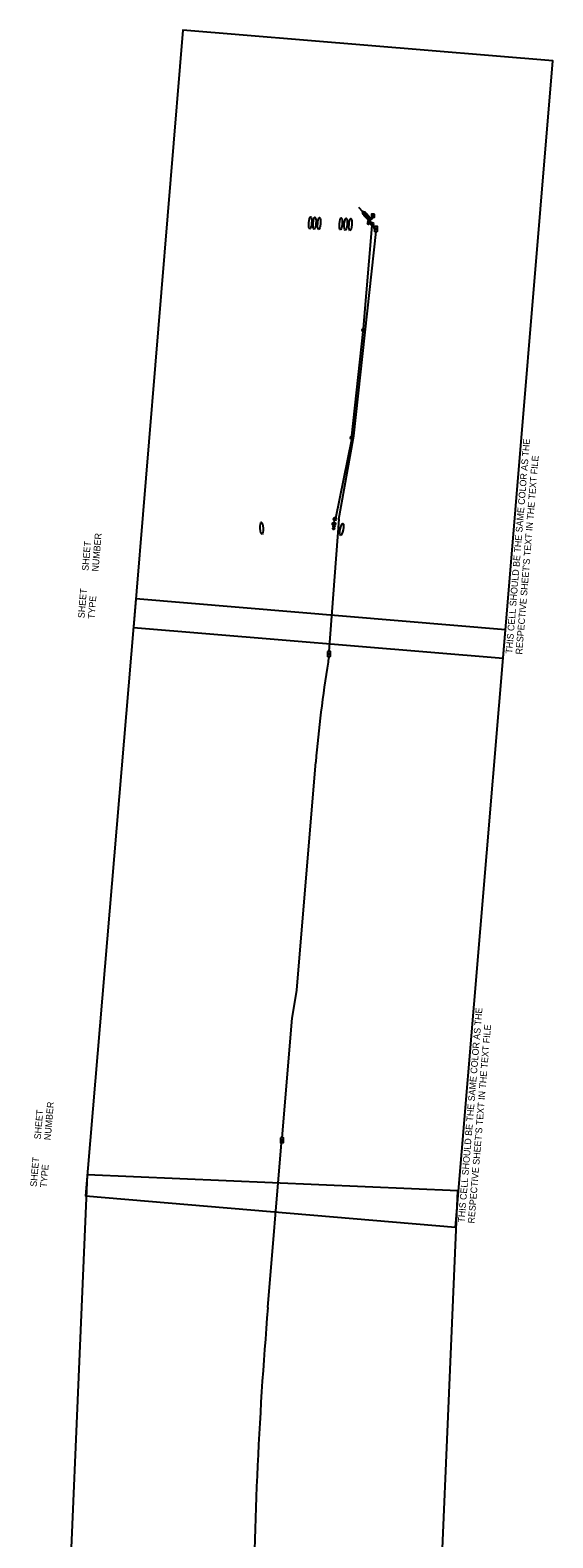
# Model space of a CAD drawing. Extents: x 601462 to 605493, y 331960 to 402715.
# Drawn here: x 602529 to 603902, y 398753 to 402715 of the extents above; entities that cross this region are included whole.
import ezdxf

# ---------------------------------------------------------------- set-up
doc = ezdxf.new("R2010")
doc.units = 0
for name, color, linetype in [('Default', 7, 'Continuous'), ('E_FTMS', 7, 'Continuous'), ('P_FTMS', 7, 'Continuous'), ('P_FTMSConduit', 7, 'Continuous'), ('P_MISC_TXT_1A (Construction)', 7, 'Continuous'), ('P_MISC_TXT_1B (Construction)', 7, 'Continuous')]:
    doc.layers.add(name, color=color, linetype=linetype)

# ---------------------------------------------------------------- blocks, each defined once
blk = doc.blocks.new('POINT_DISPLAY')
at = {"layer": 'Default'}
blk.add_line((0, 0), (0, 0), dxfattribs=at)
blk = doc.blocks.new('_U229')
at = {"layer": 'P_FTMS'}
for p, q in [((-5, 3), (2, 0)), ((-2, 3), (-4, 0)), ((-2, 3), (-4, 0)), ((-2, 3), (-4, 1)), ((-3, 3), (-4, 1)), ((-3, 3), (-4, 1)), ((-3, 3), (-4, 2)), ((-4, 3), (-4, 2)), ((-4, 3), (-4, 3)), ((-4, 3), (2, 0)), ((-4, 3), (2, 0)), ((-4, 3), (1, 0)), ((-4, 2), (1, -1)), ((-4, 2), (1, -1)), ((-4, 2), (0, -1)), ((-4, 1), (0, -1)), ((-4, 1), (0, -1)), ((-4, 0), (0, -2)), ((1, 3), (-3, -3)), ((0, 3), (-3, -3)), ((0, 3), (-3, -2)), ((0, 3), (-3, -2)), ((-1, 3), (-3, -2)), ((-1, 3), (-3, -1)), ((-1, 3), (-3, -1)), ((-3, 3), (2, 0)), ((1, 3), (-2, -3)), ((1, 3), (-2, -3)), ((-2, 3), (3, 1)), ((2, 3), (-1, -2)), ((2, 3), (-1, -2)), ((-1, 3), (3, 1)), ((2, 3), (0, -1)), ((0, 3), (3, 1)), ((3, 3), (1, -1)), ((1, 3), (4, 1)), ((1, 3), (3, 1)), ((3, 2), (1, 0)), ((2, 3), (4, 2)), ((3, 2), (2, 0)), ((4, 2), (3, 1)), ((4, 2), (3, 1)), ((3, 2), (4, 2)), ((4, 2), (4, 2)), ((4, 2), (4, 2)), ((-4, 0), (-1, -2)), ((-3, 0), (-1, -2)), ((-3, -1), (-1, -2)), ((-3, -1), (-1, -2)), ((-3, -2), (-2, -3)), ((-3, -2), (-2, -3)), ((-3, -3), (-2, -3)), ((-3, -3), (-2, -3)), ((-3, -3), (-3, -3))]:
    blk.add_line(p, q, dxfattribs=at)
blk.add_lwpolyline([(-5, 4), (5, 2), (-3, -4)], close=True, dxfattribs=at)
blk.add_blockref('POINT_DISPLAY', (5, 2), dxfattribs=at)
blk = doc.blocks.new('FMD')
at = {"layer": 'P_FTMS'}
for p, q in [((17, 18), (-17, 18)), ((-16, 16), (-16, 18)), ((16, 16), (-16, 16)), ((-15, 15), (-15, 20)), ((15, 19), (-15, 19)), ((15, 15), (-15, 15)), ((14, 20), (-14, 20)), ((13, 22), (-13, 22)), ((-13, 13), (-13, 21)), ((13, 13), (-13, 13)), ((-12, 12), (-12, 23)), ((12, 12), (-12, 12)), ((11, 23), (-11, 23)), ((10, 25), (-10, 25)), ((-10, 10), (-10, 24)), ((10, 10), (-10, 10)), ((-9, 9), (-9, 26)), ((9, 9), (-9, 9)), ((8, 26), (-8, 26)), ((7, 28), (-7, 28)), ((-7, 7), (-7, 27)), ((7, 7), (-7, 7)), ((-6, 6), (-6, 29)), ((6, 6), (-6, 6)), ((5, 29), (-5, 29)), ((4, 31), (-4, 31)), ((-4, 4), (-4, 30)), ((4, 4), (-4, 4)), ((-3, 3), (-3, 32)), ((3, 3), (-3, 3)), ((2, 32), (-2, 32)), ((1, 34), (-1, 34)), ((-1, 1), (-1, 33)), ((1, 1), (-1, 1)), ((0, 0), (0, 34)), ((1, 1), (1, 33)), ((3, 3), (3, 32)), ((4, 4), (4, 30)), ((6, 6), (6, 29)), ((7, 7), (7, 27)), ((9, 9), (9, 26)), ((10, 10), (10, 24)), ((12, 12), (12, 23)), ((13, 13), (13, 21)), ((15, 15), (15, 20)), ((16, 16), (16, 18))]:
    blk.add_line(p, q, dxfattribs=at)
blk.add_lwpolyline([(-17, 17), (0, 34), (17, 17), (0, 0)], close=True, dxfattribs=at)
blk = doc.blocks.new('FMB_2')
at = {"layer": 'P_FTMS'}
for p, q in [((24, -24), (-24, 24)), ((-24, -24), (24, 24))]:
    blk.add_line(p, q, dxfattribs=at)
blk.add_lwpolyline([(24, -24), (24, 24), (-24, 24), (-24, -24)], close=True, dxfattribs=at)
blk = doc.blocks.new('FTMS_FCV')
at = {"layer": 'P_FTMS'}
blk.add_line((13, 16), (1, -22), dxfattribs=at)
blk.add_lwpolyline([(39, 24), (-39, 24), (-39, -24), (39, -24)], close=True, dxfattribs=at)
blk.add_lwpolyline([(-12, 16), (1, -22)], dxfattribs=at)
blk = doc.blocks.new('_U231')
at = {"layer": 'P_FTMS'}
for p, q in [((11, 5), (-12, 4)), ((11, 4), (-12, 3)), ((12, 4), (-12, 2)), ((12, 3), (-12, 1)), ((-12, 3), (-11, -4)), ((12, 2), (-12, 1)), ((12, 2), (-12, 0)), ((12, 1), (-12, -1)), ((12, 0), (-12, -2)), ((10, 7), (-11, 6)), ((10, 7), (-11, 5)), ((11, 6), (-11, 4)), ((-11, 6), (-10, -7)), ((-11, 4), (-11, -6)), ((9, 9), (-10, 7)), ((9, 8), (-10, 7)), ((-10, 7), (-9, -8)), ((8, 9), (-9, 8)), ((-9, 9), (-7, -10)), ((-9, 8), (-8, -9)), ((7, 10), (-8, 9)), ((-8, 9), (-7, -10)), ((6, 11), (-7, 10)), ((-7, 10), (-5, -11)), ((-7, 10), (-6, -11)), ((4, 11), (-6, 11)), ((-6, 11), (-4, -11)), ((-5, 11), (-4, -12)), ((2, 12), (-4, 11)), ((-4, 12), (-2, -12)), ((-4, 11), (-3, -12)), ((-3, 12), (-1, -12)), ((-2, 12), (0, -12)), ((-2, 12), (-1, -12)), ((-1, 12), (1, -12)), ((0, 12), (2, -12)), ((1, 12), (3, -12)), ((1, 12), (2, -12)), ((2, 12), (4, -12)), ((3, 12), (4, -11)), ((4, 12), (5, -11)), ((4, 11), (6, -11)), ((5, 11), (7, -10)), ((6, 11), (7, -10)), ((7, 10), (9, -9)), ((7, 10), (8, -9)), ((8, 9), (9, -8)), ((9, 8), (10, -7)), ((10, 7), (11, -6)), ((11, 6), (11, -4)), ((11, 4), (12, -2)), ((12, -1), (-12, -2)), ((12, -1), (-12, -3)), ((12, -2), (-12, -4)), ((12, -3), (-11, -4)), ((12, -4), (-11, -5)), ((11, -4), (-11, -6)), ((11, -5), (-10, -7)), ((11, -6), (-10, -7)), ((10, -7), (-9, -8)), ((10, -7), (-9, -9)), ((9, -8), (-8, -9)), ((8, -9), (-7, -10)), ((7, -10), (-6, -11)), ((6, -11), (-5, -11)), ((4, -11), (-3, -12))]:
    blk.add_line(p, q, dxfattribs=at)
blk.add_circle((0, 0), 12.2, dxfattribs=at)

msp = doc.modelspace()

# ---------------------------------------------------------------- linework, layer by layer
at = {"layer": 'P_FTMS'}
for p, q in [((603391.7, 402249.5), (603402, 402238.4)), ((603402, 402238.4), (603402, 402238.4)), ((603402.1, 402238.2), (603402.9, 402238.2)), ((603402.1, 402237.9), (603403.8, 402237.9)), ((603402.2, 402237.5), (603402.3, 402238.4)), ((603402.2, 402237.7), (603404.7, 402237.6)), ((603402.3, 402237.5), (603405.6, 402237.3)), ((603402.3, 402237.2), (603406.5, 402237.1)), ((603402.4, 402237), (603407.4, 402236.8)), ((603402.4, 402236.7), (603408.2, 402236.5)), ((603402.5, 402236.6), (603402.5, 402238.3)), ((603402.5, 402236.5), (603409.1, 402236.3)), ((603402.5, 402236.3), (603409.5, 402236)), ((603402.6, 402236), (603409.3, 402235.8)), ((603402.7, 402235.7), (603402.7, 402238.2)), ((603402.7, 402235.8), (603409.1, 402235.6)), ((603402.7, 402235.5), (603408.8, 402235.3)), ((603402.8, 402235.3), (603408.6, 402235.1)), ((603402.8, 402235), (603408.3, 402234.9)), ((603402.9, 402234.8), (603403, 402238.1)), ((603402.9, 402234.8), (603408.1, 402234.6)), ((603402.9, 402234.6), (603407.8, 402234.4)), ((603403, 402234.3), (603407.6, 402234.2)), ((603403, 402234.1), (603407.3, 402233.9)), ((603403.1, 402233.9), (603403.2, 402238.1)), ((603403.1, 402233.8), (603407.1, 402233.7)), ((603403.2, 402233.6), (603406.8, 402233.5)), ((603403.2, 402233.3), (603406.6, 402233.2)), ((603403.3, 402233), (603403.5, 402238)), ((603403.3, 402233.1), (603406.3, 402233)), ((603403.3, 402232.9), (603406.1, 402232.8)), ((603403.4, 402232.6), (603405.8, 402232.5)), ((603403.4, 402232.4), (603405.6, 402232.3)), ((603403.5, 402232.1), (603403.7, 402237.9)), ((603403.5, 402232.1), (603405.3, 402232.1)), ((603403.6, 402231.9), (603405.1, 402231.8)), ((603403.6, 402231.7), (603404.8, 402231.6)), ((603403.7, 402231.2), (603403.9, 402237.9)), ((603403.7, 402231.4), (603404.6, 402231.4)), ((603403.7, 402231.2), (603404.3, 402231.1)), ((603403.8, 402230.9), (603404.1, 402230.9)), ((603403.8, 402230.7), (603403.8, 402230.7)), ((603403.9, 402230.8), (603404.2, 402237.8)), ((603404.2, 402231), (603404.4, 402237.7)), ((603404.4, 402231.2), (603404.7, 402237.6)), ((603404.7, 402231.5), (603404.9, 402237.6)), ((603404.9, 402231.7), (603405.1, 402237.5)), ((603405.2, 402231.9), (603405.4, 402237.4)), ((603405.4, 402232.2), (603405.6, 402237.3)), ((603405.7, 402232.4), (603405.8, 402237.3)), ((603405.9, 402232.6), (603406.1, 402237.2)), ((603406.2, 402232.9), (603406.3, 402237.1)), ((603406.4, 402233.1), (603406.6, 402237.1)), ((603406.6, 402227.8), (603417.9, 402227.4)), ((603406.7, 402233.3), (603406.8, 402237)), ((603409.5, 402230.5), (603406.8, 402233.4)), ((603406.8, 402228), (603417.6, 402227.6)), ((603406.8, 402227.5), (603406.8, 402228)), ((603406.8, 402227.5), (603418.1, 402227.1)), ((603406.9, 402233.6), (603407, 402236.9)), ((603407, 402227.3), (603407.1, 402228.2)), ((603407, 402227.3), (603418.3, 402226.9)), ((603407.1, 402228.2), (603417.4, 402227.9)), ((603407.2, 402233.8), (603407.3, 402236.8)), ((603407.3, 402228.4), (603417.2, 402228.1)), ((603407.3, 402227), (603407.3, 402228.4)), ((603407.3, 402227), (603418.6, 402226.6)), ((603407.4, 402234), (603407.5, 402236.8)), ((603407.5, 402226.8), (603407.6, 402228.7)), ((603407.5, 402226.8), (603418.8, 402226.4)), ((603407.6, 402228.7), (603416.9, 402228.4)), ((603407.7, 402234.2), (603407.7, 402236.7)), ((603407.7, 402226.5), (603407.8, 402228.9)), ((603407.7, 402226.5), (603419, 402226.1)), ((603407.8, 402228.9), (603416.7, 402228.6)), ((603407.9, 402234.5), (603408, 402236.6)), ((603408, 402226.3), (603408.1, 402229.1)), ((603408, 402226.3), (603419.3, 402225.9)), ((603408.1, 402229.1), (603416.5, 402228.9)), ((603408.2, 402234.7), (603408.2, 402236.5)), ((603408.2, 402226), (603408.3, 402229.4)), ((603408.2, 402226), (603419.5, 402225.6)), ((603408.3, 402229.4), (603416.2, 402229.1)), ((603408.4, 402234.9), (603408.5, 402236.5)), ((603408.4, 402225.8), (603408.5, 402229.6)), ((603408.4, 402225.8), (603419.7, 402225.4)), ((603408.5, 402229.6), (603416, 402229.4)), ((603408.6, 402235.2), (603408.7, 402236.4)), ((603408.7, 402225.5), (603408.8, 402229.8)), ((603408.7, 402225.5), (603420, 402225.1)), ((603408.8, 402229.8), (603415.8, 402229.6)), ((603408.9, 402235.4), (603408.9, 402236.3)), ((603408.9, 402225.3), (603409, 402230.1)), ((603408.9, 402225.3), (603420.2, 402224.9)), ((603409, 402230.1), (603415.6, 402229.9)), ((603409.1, 402235.6), (603409.2, 402236.3)), ((603409.1, 402225), (603409.3, 402230.3)), ((603409.1, 402225), (603420.4, 402224.6)), ((603409.3, 402224.8), (603409.5, 402230.5)), ((603409.3, 402230.3), (603415.3, 402230.1)), ((603409.3, 402224.8), (603420.6, 402224.4)), ((603409.4, 402235.9), (603409.4, 402236.2)), ((603409.5, 402230.5), (603415.1, 402230.3)), ((603409.6, 402236.1), (603409.6, 402236.1)), ((603409.6, 402224.5), (603409.8, 402230.8)), ((603409.6, 402224.5), (603420.3, 402224.2)), ((603409.8, 402224.3), (603410, 402231)), ((603409.8, 402230.8), (603414.9, 402230.6)), ((603409.8, 402224.3), (603420.1, 402223.9)), ((603410, 402224), (603410.3, 402231.2)), ((603410, 402231), (603414.6, 402230.8)), ((603410, 402224), (603419.8, 402223.7)), ((603410.3, 402223.8), (603410.5, 402231.5)), ((603410.3, 402231.2), (603414.4, 402231.1)), ((603410.3, 402223.8), (603419.6, 402223.5)), ((603410.5, 402223.5), (603410.8, 402231.7)), ((603410.5, 402231.5), (603414.2, 402231.3)), ((603410.5, 402223.5), (603419.3, 402223.2)), ((603410.7, 402223.3), (603411, 402231.9)), ((603410.7, 402223.3), (603419.1, 402223)), ((603410.8, 402231.7), (603413.9, 402231.6)), ((603411, 402223), (603411.3, 402232.2)), ((603411, 402231.9), (603413.7, 402231.8)), ((603411, 402223), (603418.8, 402222.8)), ((603411.2, 402222.8), (603411.5, 402232.4)), ((603411.2, 402222.8), (603418.6, 402222.5)), ((603411.3, 402232.2), (603413.5, 402232.1)), ((603411.4, 402222.5), (603411.8, 402232.6)), ((603411.4, 402222.5), (603418.3, 402222.3)), ((603411.5, 402232.4), (603413.2, 402232.3)), ((603411.7, 402222.3), (603412, 402232.9)), ((603411.7, 402222.3), (603418.1, 402222.1)), ((603411.8, 402232.6), (603413, 402232.6)), ((603411.9, 402222.1), (603412.3, 402233.1)), ((603411.9, 402222.1), (603417.8, 402221.9)), ((603412, 402232.9), (603412.8, 402232.8)), ((603412.1, 402221.8), (603412.5, 402233.1)), ((603412.1, 402221.8), (603417.6, 402221.6)), ((603412.3, 402233.1), (603412.5, 402233.1)), ((603412.4, 402221.6), (603412.7, 402232.9)), ((603412.4, 402221.6), (603417.3, 402221.4)), ((603412.6, 402221.3), (603413, 402232.6)), ((603412.6, 402221.3), (603417.1, 402221.2)), ((603412.8, 402221.1), (603413.2, 402232.4)), ((603412.8, 402221.1), (603416.8, 402220.9)), ((603413.1, 402220.8), (603413.4, 402232.1)), ((603413.1, 402220.8), (603416.6, 402220.7)), ((603413.3, 402220.6), (603413.7, 402231.9)), ((603413.3, 402220.6), (603416.3, 402220.5)), ((603413.5, 402220.3), (603413.9, 402231.6)), ((603413.5, 402220.3), (603416.1, 402220.2)), ((603413.8, 402220.1), (603414.1, 402231.4)), ((603413.8, 402220.1), (603415.8, 402220)), ((603414, 402219.8), (603414.4, 402231.1)), ((603414, 402219.8), (603415.6, 402219.8)), ((603414.2, 402219.6), (603414.6, 402230.9)), ((603414.2, 402219.6), (603415.3, 402219.5)), ((603414.4, 402219.3), (603414.8, 402230.6)), ((603414.4, 402225.2), (603414.6, 402225)), ((603414.4, 402225.2), (603414.4, 402225.2)), ((603414.4, 402219.3), (603415.1, 402219.3)), ((603414.7, 402219.1), (603415.1, 402230.4)), ((603414.7, 402219.1), (603414.8, 402219.1)), ((603414.9, 402219.1), (603415.3, 402230.1)), ((603415.2, 402219.4), (603415.5, 402229.9)), ((603415.4, 402219.6), (603415.8, 402229.6)), ((603415.7, 402219.8), (603416, 402229.4)), ((603415.9, 402220.1), (603416.2, 402229.1)), ((603416.2, 402220.3), (603416.4, 402228.9)), ((603416.4, 402220.5), (603416.7, 402228.6)), ((603416.4, 402219.2), (603424.4, 402218.9)), ((603416.4, 402218.9), (603424.4, 402218.7)), ((603416.4, 402218.7), (603424.4, 402218.4)), ((603416.4, 402218.4), (603424.4, 402218.2)), ((603416.5, 402217.9), (603416.6, 402220)), ((603416.5, 402219.6), (603424.4, 402219.4)), ((603416.5, 402219.4), (603424.4, 402219.1)), ((603416.5, 402218.2), (603424.3, 402217.9)), ((603416.5, 402218), (603424.3, 402217.7)), ((603416.6, 402220.1), (603424.3, 402219.9)), ((603416.6, 402219.9), (603424.3, 402219.6)), ((603416.6, 402217.7), (603424.2, 402217.5)), ((603416.6, 402217.5), (603424.1, 402217.2)), ((603416.7, 402220.8), (603416.9, 402228.4)), ((603416.7, 402220.4), (603424.2, 402220.1)), ((603416.7, 402217.2), (603424, 402217)), ((603416.8, 402217.2), (603416.9, 402220.6)), ((603416.9, 402221), (603417.1, 402228.2)), ((603416.9, 402220.6), (603424.1, 402220.4)), ((603416.9, 402217), (603423.8, 402216.8)), ((603417, 402216.8), (603417.1, 402221.1)), ((603417, 402220.8), (603424, 402220.6)), ((603417, 402216.7), (603423.7, 402216.5)), ((603417.1, 402221.1), (603423.8, 402220.8)), ((603417.2, 402221.2), (603417.4, 402227.9)), ((603417.2, 402216.4), (603417.4, 402221.4)), ((603417.2, 402216.5), (603423.5, 402216.3)), ((603417.3, 402221.3), (603423.7, 402221.1)), ((603417.3, 402216.3), (603423.3, 402216.1)), ((603417.4, 402221.5), (603417.6, 402227.7)), ((603417.4, 402216.1), (603417.6, 402221.6)), ((603417.5, 402221.5), (603423.5, 402221.3)), ((603417.6, 402221.7), (603417.8, 402227.4)), ((603417.6, 402216), (603423.1, 402215.8)), ((603417.7, 402215.9), (603417.9, 402221.9)), ((603417.7, 402221.8), (603423.3, 402221.6)), ((603417.8, 402215.8), (603422.8, 402215.6)), ((603417.9, 402221.9), (603418.1, 402227.2)), ((603417.9, 402215.7), (603418.1, 402222.1)), ((603418, 402222), (603423, 402221.8)), ((603418.1, 402222.1), (603418.3, 402226.9)), ((603418.1, 402215.5), (603418.4, 402222.2)), ((603418.2, 402215.5), (603422.4, 402215.4)), ((603418.4, 402222.4), (603418.5, 402226.7)), ((603418.4, 402215.4), (603418.6, 402222.4)), ((603418.4, 402222.2), (603422.7, 402222.1)), ((603418.6, 402222.6), (603418.8, 402226.4)), ((603418.6, 402215.2), (603418.9, 402222.5)), ((603418.6, 402215.3), (603422, 402215.1)), ((603418.8, 402215.1), (603419.1, 402222.6)), ((603418.8, 402222.5), (603422.3, 402222.3)), ((603418.9, 402222.8), (603419, 402226.2)), ((603419.1, 402223.1), (603419.2, 402225.9)), ((603419.1, 402215), (603419.3, 402222.6)), ((603419.2, 402215), (603421.4, 402214.9)), ((603419.3, 402215), (603419.6, 402222.7)), ((603419.4, 402223.3), (603419.5, 402225.7)), ((603419.5, 402222.7), (603421.7, 402222.6)), ((603419.6, 402223.5), (603419.7, 402225.4)), ((603419.6, 402214.9), (603419.8, 402222.7)), ((603419.8, 402214.9), (603420.1, 402222.8)), ((603419.9, 402223.8), (603419.9, 402225.2)), ((603420, 402214.8), (603420.3, 402222.8)), ((603420.1, 402224), (603420.2, 402224.9)), ((603420.3, 402214.8), (603420.5, 402222.8)), ((603420.4, 402224.2), (603420.4, 402224.7)), ((603420.5, 402214.8), (603420.8, 402222.8)), ((603420.8, 402214.8), (603421, 402222.7)), ((603421, 402214.8), (603421.3, 402222.7)), ((603421.2, 402214.9), (603421.5, 402222.6)), ((603421.5, 402214.9), (603421.7, 402222.6)), ((603421.7, 402215), (603422, 402222.5)), ((603422, 402215.1), (603422.2, 402222.4)), ((603422.2, 402215.2), (603422.5, 402222.2)), ((603422.5, 402215.4), (603422.7, 402222.1)), ((603422.7, 402215.5), (603422.9, 402221.9)), ((603423, 402215.7), (603423.2, 402221.7)), ((603423.2, 402215.9), (603423.4, 402221.5)), ((603423.4, 402216.2), (603423.6, 402221.2)), ((603423.7, 402216.5), (603423.8, 402220.8)), ((603424, 402217), (603424.1, 402220.4)), ((603424.2, 402217.6), (603424.3, 402219.8))]:
    msp.add_line(p, q, dxfattribs=at)
for points in [[(603403.8, 402230.7), (603409.7, 402236.1), (603402, 402238.4)], [(603420.6, 402224.5), (603412.4, 402233.2), (603406.6, 402227.8), (603414.8, 402219)]]:
    msp.add_lwpolyline(points, close=True, dxfattribs=at)
for centre, radius in [((603420.4, 402218.8), 4), ((603427.4, 402205.8), 3.75), ((603404.8, 401926.8), 3.75), ((603374.2, 401644.1), 3.75), ((603329.3, 401430.3), 3.75)]:
    msp.add_circle(centre, radius, dxfattribs=at)
for centre, start, end in [((603427.1, 402201.3), 32.6299, 138.8855), ((603427.7, 402210.3), 212.6299, 318.8855), ((603404.5, 401922.3), 32.6299, 138.8855), ((603405.2, 401931.3), 212.6299, 318.8855), ((603373.9, 401639.7), 32.6299, 138.8855), ((603374.6, 401648.6), 212.6299, 318.8855), ((603329, 401425.8), 32.6299, 138.8855), ((603329.7, 401434.8), 212.6299, 318.8855)]:
    msp.add_arc(centre, 3.75, start, end, dxfattribs=at)
for centre, major_axis in [((603264.9, 402208.5), (-1.2, -15.9)), ((603276.2, 402207.6), (-1.2, -15.9)), ((603288.2, 402206.7), (-1.2, -15.9)), ((603345.3, 402205.9), (-1.2, -15.9)), ((603358.1, 402204.9), (-1.2, -15.9)), ((603370.5, 402203.9), (-1.2, -15.9)), ((603137.2, 401405.8), (1, -16)), ((603347.6, 401402.7), (-3.2, -15.7))]:
    msp.add_ellipse(centre, major_axis=major_axis, ratio=0.23471, dxfattribs=at)
at = {"layer": 'P_FTMSConduit'}
for p, q in [((603424.6, 402208.3), (603420.3, 402215)), ((603429.8, 402223.8), (603429.6, 402219.7)), ((603379, 401648.6), (603438, 402186.3)), ((603405, 401930.6), (603427.4, 402202.1)), ((603433.9, 402192.7), (603430.2, 402203.4)), ((603374.6, 401648.6), (603404.3, 401923.1)), ((603332.5, 401432.3), (603373.9, 401639.7)), ((603339.8, 401429.9), (603379, 401648.6)), ((603328.2, 401421.3), (603328.4, 401426.6)), ((603229.4, 400192.8), (603279.4, 400791)), ((603217.1, 400117.9), (603229.3, 400192.2)), ((603190.9, 399804.1), (603217.2, 400118.6)), ((603153.6, 399358.1), (603189.8, 399791.3))]:
    msp.add_line(p, q, dxfattribs=at)
msp.add_lwpolyline([(603339.8, 401429.9), (603313.9, 401082.3)], dxfattribs=at)
for centre, radius, start, end in [((603573.8, 401019.5), 264.5, 169.0953, 172.411), ((606751.4, 400500.6), 3484.1, 170.8534, 175.2178), ((614541.5, 398405.4), 11427.7, 175.21781, 179.66703)]:
    msp.add_arc(centre, radius, start, end, dxfattribs=at)
at = {"layer": 'P_MISC_TXT_1A (Construction)'}
msp.add_lwpolyline([(603646.3, 399569.6), (603778.1, 401139.1), (602806.5, 401220.7), (602674.8, 399651.2)], close=True, dxfattribs=at)
msp.add_lwpolyline([(603646.3, 399569.6), (603778.1, 401139.1), (602806.5, 401220.7), (602674.8, 399651.2)], close=True, dxfattribs=at)
at = {"layer": 'P_MISC_TXT_1B (Construction)'}
for points in [[(603771.9, 401064.8), (603902.2, 402634.4), (602930.6, 402715.1), (602800.2, 401145.5)], [(603771.9, 401064.8), (603902.2, 402634.4), (602930.6, 402715.1), (602800.2, 401145.5)], [(603585.5, 398091.6), (603652.9, 399665.1), (602678.8, 399706.9), (602611.4, 398133.3)], [(603585.5, 398091.6), (603652.9, 399665.1), (602678.8, 399706.9), (602611.4, 398133.3)]]:
    msp.add_lwpolyline(points, close=True, dxfattribs=at)

# ---------------------------------------------------------------- block references
at = {"layer": 'E_FTMS', "xscale": 0.16401569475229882, "yscale": 0.16401569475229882, "rotation": 88.55476651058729}
msp.add_blockref('FMB_2', (603429.9, 402227.8), dxfattribs=at)
at = {"layer": 'P_FTMS'}
for name, p, xscale, yscale, rotation in [('FMD', (603421.5, 402212.2), 0.16404166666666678, 0.16404166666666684, 81.10108204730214), ('_U229', (603426.6, 402218.9), 0.1968499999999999, 0.19684999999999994, -160.1813995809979), ('FMD', (603420.6, 402206.6), 0.16404166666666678, 0.16404166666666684, 81.10108204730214), ('FTMS_FCV', (603437.9, 402192.8), 0.16404166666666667, 0.1640416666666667, 90.75145918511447), ('_U231', (603327.2, 401417.4), 0.32808333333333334, 0.32808333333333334, 175.753765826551), ('FMD', (603328.8, 401404.6), 0.16404166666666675, 0.16404166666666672, 81.64663005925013), ('FMD', (603329.6, 401410.2), 0.16404166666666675, 0.16404166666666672, 81.64663005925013), ('FTMS_FCV', (603314, 401075.9), 0.16404166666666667, 0.1640416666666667, 90.75145918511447), ('FTMS_FCV', (603191, 399797.7), 0.16404166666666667, 0.1640416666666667, 90.75145918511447)]:
    msp.add_blockref(name, p, dxfattribs=dict(at, xscale=xscale, yscale=yscale, rotation=rotation))

# ---------------------------------------------------------------- texts
at = {"layer": 'P_MISC_TXT_1A (Construction)'}
for s, p in [('THIS CELL SHOULD BE THE SAME COLOR AS THE', (603670, 399580.6)), ('THIS CELL SHOULD BE THE SAME COLOR AS THE', (603670, 399580.6)), ("RESPECTIVE SHEET'S TEXT IN THE TEXT FILE", (603696.1, 399578.5)), ("RESPECTIVE SHEET'S TEXT IN THE TEXT FILE", (603696.1, 399578.5)), ('SHEET', (602556.9, 399799.5)), ('SHEET', (602556.9, 399799.5)), ('NUMBER', (602583, 399797.3)), ('NUMBER', (602583, 399797.3)), ('SHEET', (602546.4, 399674.9)), ('SHEET', (602546.4, 399674.9)), ('TYPE', (602572.6, 399672.7)), ('TYPE', (602572.6, 399672.7))]:
    msp.add_text(s, height=17.5, rotation=85.2028, dxfattribs=at).set_placement(p)
at = {"layer": 'P_MISC_TXT_1B (Construction)'}
for s, p in [('THIS CELL SHOULD BE THE SAME COLOR AS THE', (603795.5, 401075.8)), ('THIS CELL SHOULD BE THE SAME COLOR AS THE', (603795.5, 401075.8)), ("RESPECTIVE SHEET'S TEXT IN THE TEXT FILE", (603821.6, 401073.7)), ("RESPECTIVE SHEET'S TEXT IN THE TEXT FILE", (603821.6, 401073.7)), ('NUMBER', (602708.4, 401291.6)), ('NUMBER', (602708.4, 401291.6)), ('SHEET', (602682.2, 401293.7)), ('SHEET', (602682.2, 401293.7)), ('SHEET', (602671.8, 401169.2)), ('SHEET', (602671.8, 401169.2)), ('TYPE', (602698, 401167)), ('TYPE', (602698, 401167))]:
    msp.add_text(s, height=17.5, rotation=85.2525, dxfattribs=at).set_placement(p)

doc.saveas('drawing.dxf')
